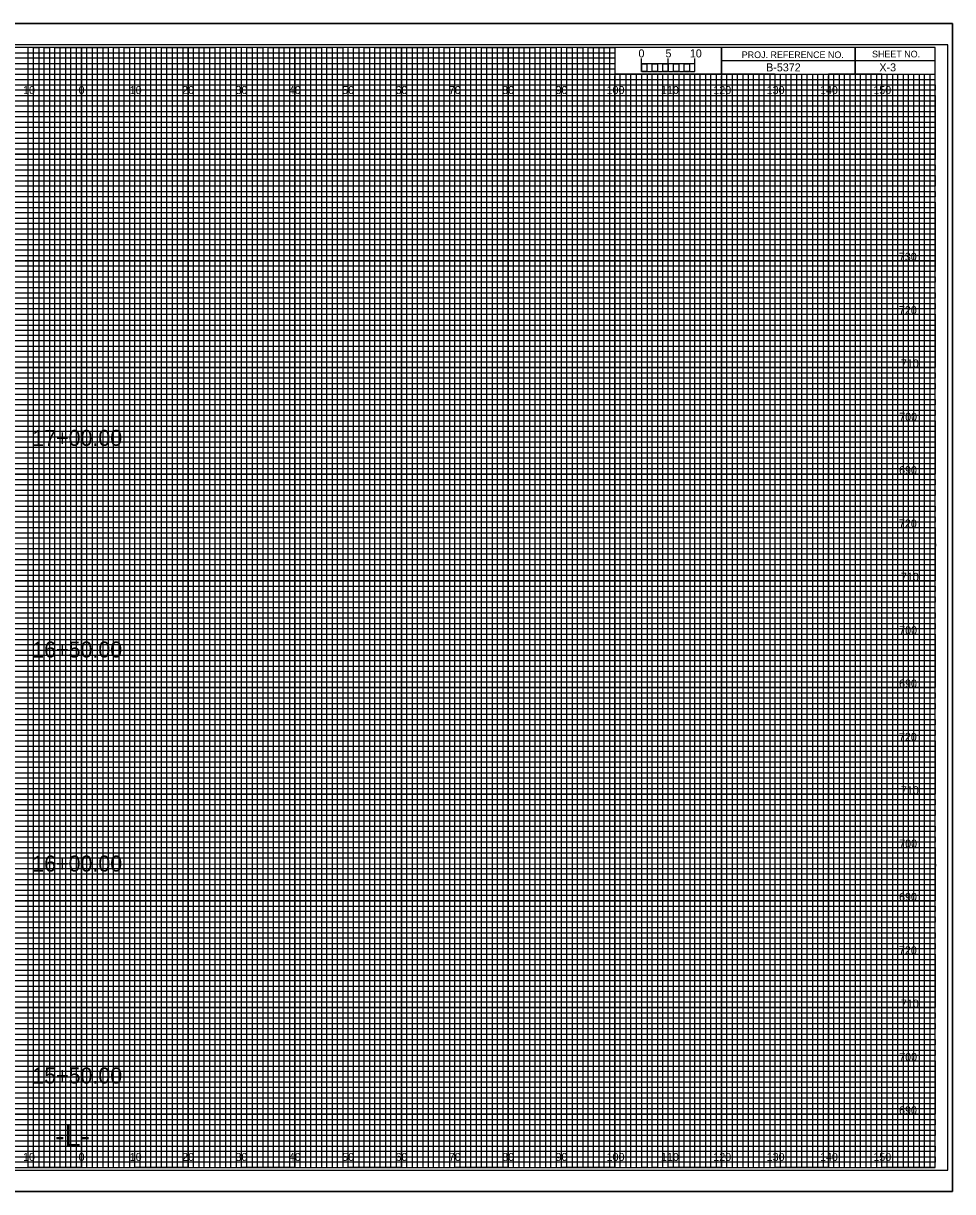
# Model space of a CAD drawing. Extents: x -98 to 717, y -10 to 1974.
# Drawn here: x 149.1 to 323.3, y 435.5 to 654.5 of the extents above; entities that cross this region are included whole.
import ezdxf

# ---------------------------------------------------------------- set-up
doc = ezdxf.new("R2010")
doc.units = 0
for name, color, linetype in [('Default', 7, 'Continuous'), ('Exist XS Center Line Elevation Label', 7, 'Continuous'), ('Prop CMT Conc Surface', 7, 'Continuous'), ('Prop CMT Concrete Structures', 7, 'Continuous'), ('Prop CMT Pvmt Course 1', 7, 'Continuous'), ('Prop CMT Pvmt Course 1 CG', 7, 'Continuous'), ('Prop CMT Pvmt Course 2', 7, 'Continuous'), ('Prop CMT Pvmt Course 3', 7, 'Continuous'), ('Prop CMT Pvmt Surface', 7, 'Continuous'), ('Prop CMT Pvmt Surface Shoulder', 7, 'Continuous'), ('Prop CMT Shld Paved Course 1', 7, 'Continuous'), ('Prop CMT Shld Paved Course 2', 7, 'Continuous'), ('Prop CMT Shld Paved Course 3', 7, 'Continuous'), ('Prop CMT Slope Grass', 7, 'Continuous'), ('Prop CMT Subgrade Earthwork', 7, 'Continuous'), ('Prop XS Earthwork Shape', 7, 'Continuous'), ('Prop XS Elevation Labels', 7, 'Continuous'), ('Typical Curb CELL', 7, 'Continuous')]:
    doc.layers.add(name, color=color, linetype=linetype)

msp = doc.modelspace()

# ---------------------------------------------------------------- linework, layer by layer
at = {"layer": 'Default'}
msp.add_lwpolyline([(323.3, 435.5), (-13.4, 435.5), (-13.4, 654.5), (323.3, 654.5)], close=True, dxfattribs=at)
at = {"layer": 'Exist XS Center Line Elevation Label'}
for p, q in [((0, 649), (260, 649)), ((260, 649), (260, 647.98)), ((260, 647.98), (0, 647.98)), ((0, 647), (260, 647)), ((260, 647), (260, 645.89)), ((260, 645.89), (0, 645.89)), ((0, 644), (320, 644))]:
    msp.add_line(p, q, dxfattribs=at)
for points in [[(0, 643), (270, 643), (320, 643), (320, 642), (0, 642)], [(0, 641), (320, 641), (320, 639), (0, 639)], [(0, 638), (320, 638), (320, 637), (0, 636.98)], [(0, 636), (320, 636), (320, 634), (0, 634)], [(0, 633), (320, 633), (320, 632), (0, 632)], [(0, 631), (320, 631), (320, 629), (0, 629)], [(0, 628), (320, 628), (320, 627), (0, 627)], [(0, 626), (320, 626), (320, 624), (0, 624)], [(0, 623), (320, 623), (320, 622), (0, 622)], [(0, 621), (320, 621), (320, 619), (0, 619)], [(0, 618), (320, 618), (320, 617), (0, 617)], [(0, 616), (320, 616), (320, 613.95), (320, 613), (320, 612), (0, 612)], [(0, 614), (320, 614), (320, 613), (0, 613)], [(0, 611), (320, 611), (320, 609), (0, 609.03)], [(0, 609.03), (320, 609), (320, 608), (0, 608)], [(0, 607), (320, 607), (320, 606), (0, 606)], [(0, 604), (320, 604), (320, 603), (0, 603)], [(0, 602), (320, 602), (320, 601), (0, 601)], [(-0.07, 598.89), (320, 598.89), (320, 597.88), (-0.07, 597.88)], [(0, 597), (320, 597), (320, 596), (0, 596)], [(0, 594), (320, 594), (320, 593), (0, 593)], [(0, 592), (320, 592), (320, 591), (0, 591)], [(0, 589), (320, 589), (320, 588), (0, 588)], [(0, 587), (320, 587), (320, 586), (0, 586)], [(0, 584), (320, 584), (320, 583), (0, 583)], [(0, 582), (320, 582), (320, 581), (0, 581)], [(0, 579), (320, 579), (319.99, 577.98), (0, 578)], [(0, 577), (320, 577), (320, 576), (0, 576)], [(0, 574), (320, 574), (320, 573), (0, 573)], [(0, 572), (320, 572), (320, 571), (0, 571)], [(0, 569), (320, 569), (320, 568), (0, 568)], [(0, 567), (320, 567), (320, 566), (0, 566)], [(0, 564), (320, 564), (320, 563), (0, 563)], [(0, 562), (320, 562), (320, 561), (0, 561)], [(0, 559), (320, 559), (320, 558), (0, 558)], [(0, 556.99), (320.07, 556.91), (320, 556), (0, 556)], [(0, 554), (320, 554), (320, 553), (0, 553)], [(0, 552), (320, 552), (320, 551), (0, 551)], [(0, 549), (320, 549), (320, 548), (0, 548)], [(0, 547), (320, 547), (320, 546), (0, 546)], [(0, 544), (320, 544), (320, 543), (0, 543)], [(0, 542), (320, 542), (320, 541), (0, 541)], [(0, 539), (320, 539), (320, 538), (0, 538)], [(0, 537), (320, 537), (320, 536), (0, 536)], [(0, 534), (320, 534), (320, 533), (0, 533)], [(0, 532), (320, 532), (320, 531), (0, 531)], [(0, 529), (320, 529), (320, 528), (0, 528)], [(0, 527), (320, 527), (320, 526), (0, 526)], [(0, 524), (320, 524), (320, 523), (0, 523)], [(0, 522), (320, 522), (320, 521), (0, 521)], [(0, 519), (320, 519), (319.99, 517.98), (0, 518)], [(0, 517), (320, 517), (320, 516), (0, 516)], [(0, 514), (320, 514), (320, 513), (0, 513)], [(0, 512), (320, 512), (320, 511), (0, 511)], [(0, 509), (320, 509), (320, 508), (0, 508)], [(0, 507), (320, 507), (320, 506), (0, 506)], [(0, 504), (320, 504), (320, 503), (0, 503)], [(0, 502), (320, 502), (320, 501), (0, 501)], [(0, 499), (320, 499), (320, 498), (0, 498)], [(0, 496.99), (320.07, 496.91), (320, 496), (0, 496)], [(0, 494), (320, 494), (320, 493), (0, 493)], [(0, 492), (320, 492), (320, 491), (0, 491)], [(0, 489), (320, 489), (320, 488), (0, 488)], [(0, 487), (320, 487), (320, 486), (0, 486)], [(0, 484), (320, 484), (320, 483), (0, 483)], [(0, 482), (320, 482), (320, 481), (0, 481)], [(0, 479), (320, 479), (320, 478), (0, 478)], [(0, 477), (320, 477), (320, 476), (0, 476)], [(0, 474), (320, 474), (320, 473), (0, 473)], [(0, 472), (320, 472), (320, 471), (0, 471)], [(0, 469), (320, 469), (320, 468), (0, 468)], [(0, 467), (320, 467), (320, 466), (0, 466)], [(0, 464), (320, 464), (320, 463), (0, 463)], [(0, 462), (320, 462), (320, 461), (0, 461)], [(0, 459), (320, 459), (320, 458), (0, 458)], [(0, 457), (320, 457), (320, 456), (0, 456)], [(0, 454), (320, 454), (320, 453), (0, 453)], [(0, 452), (320, 452), (320, 451), (0, 451)], [(0, 449), (320, 449), (320, 448), (0, 448)], [(0, 447), (320, 447), (320, 446), (0, 446)], [(0, 444), (320, 444), (320, 443), (0, 443)], [(0, 442), (320, 442), (320, 441), (0, 441)]]:
    msp.add_lwpolyline(points, dxfattribs=at)
at = {"layer": 'Prop CMT Conc Surface'}
for p, q in [((305, 650), (305, 645)), ((305, 645), (305, 650)), ((280, 647.5), (280, 645)), ((320, 647.49), (280, 647.49)), ((280, 645), (320, 645))]:
    msp.add_line(p, q, dxfattribs=at)
for points in [[(320, 650), (0, 650), (0, 440), (320, 440)], [(280, 650), (260, 650), (260, 645.03), (280, 645.03)], [(320, 650), (280, 650), (280, 645), (320, 645)]]:
    msp.add_lwpolyline(points, close=True, dxfattribs=at)
at = {"layer": 'Prop CMT Concrete Structures'}
for p, q in [((150, 440), (150, 650)), ((160, 440), (160, 650)), ((170, 440), (170, 650)), ((180, 440), (180, 650)), ((190, 440), (190, 650)), ((200, 440), (200, 650)), ((210, 440), (210, 650)), ((220, 440), (220, 650)), ((230, 440), (230, 650)), ((240, 440), (240, 650)), ((250, 440), (250, 650)), ((260, 440), (260, 644.69)), ((270, 440), (270, 644.69)), ((280, 440), (280, 644.69)), ((290, 440), (290, 644.69)), ((300, 440), (300, 644.69)), ((310, 440), (310, 644.69)), ((0, 640), (320, 640)), ((0, 630), (320, 630)), ((0, 620), (320, 620)), ((0, 610), (320, 610)), ((0, 600), (320, 600)), ((0, 590), (320, 590)), ((0, 580), (320, 580)), ((0, 570), (320, 570)), ((0, 560), (320, 560)), ((0, 550), (320, 550)), ((0, 540), (320, 540)), ((0, 530), (320, 530)), ((0, 520), (320, 520)), ((0, 510), (320, 510)), ((0, 500), (320, 500)), ((0, 490), (320, 490)), ((0, 480), (320, 480)), ((0, 470), (320, 470)), ((0, 460), (320, 460)), ((0, 450), (320, 450))]:
    msp.add_line(p, q, dxfattribs=at)
at = {"layer": 'Prop CMT Pvmt Course 2'}
msp.add_lwpolyline([(-13.4, 435.5), (323.3, 435.5), (323.3, 654.5), (-13.4, 654.5)], close=True, dxfattribs=at)
at = {"layer": 'Prop CMT Pvmt Course 3'}
msp.add_lwpolyline([(-10.8, 439.5), (322.4, 439.5), (322.4, 650.5), (-10.8, 650.5)], close=True, dxfattribs=at)
at = {"layer": 'Prop CMT Pvmt Surface'}
for p, q in [((323.3, 654.5), (-13.4, 654.5)), ((-13.4, 435.5), (323.3, 435.5))]:
    msp.add_line(p, q, dxfattribs=at)
at = {"layer": 'Prop CMT Slope Grass'}
for p, q in [((265, 645.49), (265, 647.9)), ((265, 646.9), (265, 647.9)), ((270, 645.49), (270, 647.9)), ((275, 645.49), (275, 647.9)), ((275, 646.9), (275, 647.9))]:
    msp.add_line(p, q, dxfattribs=at)
for points in [[(275, 646.9), (265, 646.9), (265, 645.49), (275, 645.49)], [(265, 646.9), (266, 646.9), (266, 645.49), (265, 645.49)], [(267, 646.9), (268, 646.9), (268, 645.49), (267, 645.49)], [(269, 646.9), (270, 646.9), (270, 645.49), (269, 645.49)], [(271, 646.9), (272, 646.9), (272, 645.49), (271, 645.49)], [(273, 646.9), (274, 646.9), (274, 645.49), (273, 645.49)]]:
    msp.add_lwpolyline(points, close=True, dxfattribs=at)
at = {"layer": 'Prop CMT Subgrade Earthwork'}
for p, q in [((267, 645), (266.01, 645)), ((266.01, 645), (266.01, 440)), ((267, 440), (267, 645)), ((269, 645), (268, 645)), ((268, 645), (268, 440)), ((269, 440), (269, 645)), ((266.01, 440), (265, 440)), ((268, 440), (267, 440))]:
    msp.add_line(p, q, dxfattribs=at)
for points in [[(150, 440), (151, 440), (151, 650), (152, 650), (152, 440)], [(152, 440), (153, 440), (153, 650), (154, 650), (154, 440)], [(155, 440), (156, 440), (156, 650), (157, 650), (157, 440)], [(157, 440), (158, 440), (158, 650), (159, 650), (159, 440)], [(160, 440), (161, 440), (161, 650), (162, 650), (162, 440)], [(162, 440), (163, 440), (163, 650), (164, 650), (164, 440)], [(165, 440), (166, 440), (166, 650), (167, 650), (167, 440)], [(167, 440), (168, 440), (168, 650), (169, 650), (169, 440)], [(170, 440), (171, 440), (171, 650), (172, 650), (172, 440)], [(172, 440), (173, 440), (173, 650), (174, 650), (174, 440)], [(175, 440), (176, 440), (176, 650), (177, 650), (177, 440)], [(177, 440), (178, 440), (178, 650), (179, 650), (179, 440)], [(180, 440), (181, 440), (181, 650), (182, 650), (182, 440)], [(182, 440), (183, 440), (183, 650), (184, 650), (184, 440)], [(185, 440), (186, 440), (186, 650), (187, 650), (187, 440)], [(187, 440), (188, 440), (188, 650), (189, 650), (189, 440)], [(190, 440), (191, 440), (191, 650), (192, 650), (192, 440)], [(192, 440), (193, 440), (193, 650), (194, 650), (194, 440)], [(195, 440), (196, 440), (196, 650), (197, 650), (197, 440)], [(197, 440), (198, 440), (198, 650), (199, 650), (199, 440)], [(200, 440), (201, 440), (201, 650), (202, 650), (202, 440)], [(202, 440), (203, 440), (203, 650), (204, 650), (204, 440)], [(205, 440), (206, 440), (206, 650), (207, 650), (207, 440)], [(207, 440), (208, 440), (208, 650), (209, 650), (209, 440)], [(210, 440), (211, 440), (211, 650), (212, 650), (212, 440)], [(212, 440), (213, 440), (213, 650), (214, 650), (214, 440)], [(215, 440), (216, 440), (216, 650), (217, 650), (217, 440)], [(217, 440), (218, 440), (218, 650), (219, 650), (219, 440)], [(220, 440), (221, 440), (221, 650), (222, 650), (222, 440)], [(222, 440), (223, 440), (223, 650), (224, 650), (224, 440)], [(225, 440), (226, 440), (226, 650), (227, 650), (227, 440)], [(227, 440), (228, 440), (228, 650), (229, 650), (229, 440)], [(230, 440), (231, 440), (231, 650), (232, 650), (232, 440)], [(232, 440), (233, 440), (233, 650), (234, 650), (234, 440)], [(235, 440), (236, 440), (236, 650), (237, 650), (237, 440)], [(237, 440), (238, 440), (238, 650), (239, 650), (239, 440)], [(240, 440), (241, 440), (241, 650), (242, 650), (242, 440)], [(242, 440), (243, 440), (243, 650), (244, 650), (244, 440)], [(245, 440), (246, 440), (246, 650), (247, 650), (247, 440)], [(247, 440), (248, 440), (248, 650), (249, 650), (249, 440)], [(250, 440), (251, 440), (251, 650), (252, 650), (252, 440)], [(252, 440), (253, 440), (253, 650), (254, 650), (254, 440)], [(255, 440), (256, 440), (256, 650), (257, 650), (257, 440)], [(257, 440), (258, 440), (258, 650), (259, 650), (259, 440)], [(260, 440), (261, 440), (261, 645), (262.02, 645), (262.02, 440)], [(262, 440), (263, 440), (263, 645), (263.99, 645), (263.99, 440)], [(270, 440), (270.98, 440), (270.98, 645), (272, 645), (272, 440)], [(272, 440), (273, 440), (273, 645), (274.05, 645), (274.05, 440)], [(275, 440), (276, 440), (276, 645), (277, 645), (277, 440)], [(277, 440), (278, 440), (278, 645), (279, 645), (279, 440)], [(280, 440), (281, 440), (281, 645), (282, 645), (282, 440)], [(282, 440), (283, 440), (283, 645), (284, 645), (284, 440)], [(285, 440), (286, 440), (286, 645), (287, 645), (287, 440)], [(287, 440), (288, 440), (288, 645), (289, 645), (289, 440)], [(290, 440), (291, 440), (291, 645), (292, 645), (292, 440)], [(292, 440), (293, 440), (293, 645), (294, 645), (294, 440)], [(295, 440), (296, 440), (296, 645), (297, 645), (297, 440)], [(297, 440), (298, 440), (298, 645), (299, 645), (299, 440)], [(300, 440), (301, 440), (301, 645), (302, 645), (302, 440)], [(302, 440), (303, 440), (303, 645), (304, 645), (304, 440)], [(305, 440), (306, 440), (306, 645), (307, 645), (307, 440)], [(307, 440), (308, 440), (308, 645), (309, 645), (309, 440)], [(310, 440), (311, 440), (311, 645), (312, 645), (312, 440)], [(312, 440), (313, 440), (313, 645), (314, 645), (314, 440)], [(315, 440), (316, 440), (316, 645), (317, 645), (317, 440)], [(317, 440), (318, 440), (318, 645), (319, 645), (319, 440)]]:
    msp.add_lwpolyline(points, dxfattribs=at)
at = {"layer": 'Prop XS Elevation Labels'}
for p, q in [((150, 650), (140, 650)), ((150, 440), (150, 650)), ((170, 650), (160, 650)), ((160, 650), (160, 440)), ((170, 440), (170, 650)), ((190, 650), (180, 650)), ((180, 650), (180, 440)), ((190, 440), (190, 650)), ((210, 650), (200, 650)), ((200, 650), (200, 440)), ((210, 440), (210, 650)), ((230, 650), (220, 650)), ((220, 650), (220, 440)), ((230, 440), (230, 650)), ((250, 650), (240, 650)), ((240, 650), (240, 440)), ((250, 440), (250, 650)), ((260, 650), (260, 440)), ((270, 440), (270, 645)), ((290, 645), (280, 645)), ((280, 645), (280, 440)), ((290, 440), (290, 645)), ((310, 645), (300, 645)), ((300, 645), (300, 440)), ((310, 440), (310, 645)), ((160, 440), (150, 440)), ((180, 440), (170, 440)), ((200, 440), (190, 440)), ((220, 440), (210, 440)), ((240, 440), (230, 440)), ((260, 440), (250, 440)), ((280, 440), (270, 440)), ((300, 440), (290, 440)), ((320, 440), (310, 440)), ((320, 440), (320, 440))]:
    msp.add_line(p, q, dxfattribs=at)
for points in [[(0, 640), (320, 640), (320, 630), (0, 630)], [(0, 620), (320, 620), (320, 610), (0, 610)], [(0, 600), (320, 600), (320, 590), (0, 590)], [(0, 580), (320, 580), (320, 570), (0, 570)], [(0, 560), (320, 560), (320, 550), (0, 550)], [(0, 540), (320, 540), (320, 530), (0, 530)], [(0, 520), (320, 520), (320, 510), (0, 510)], [(0, 500), (320, 500), (320, 490), (0, 490)], [(0, 480), (320, 480), (320, 470), (0, 470)], [(0, 460), (320, 460), (320, 450), (0, 450)]]:
    msp.add_lwpolyline(points, dxfattribs=at)
at = {"layer": 'Typical Curb CELL'}
for points in [[(145, 440), (155, 440), (155, 650), (165, 650), (165, 440), (175, 440), (175, 650), (185, 650), (185, 440), (195, 440), (195, 650), (205, 650), (205, 440), (215, 440), (215, 650), (225, 650), (225, 440), (235, 440), (235, 650), (245, 650), (245, 440), (255, 440), (255, 650), (259.93, 650), (260, 650), (260, 645), (264.99, 645), (264.99, 440), (275, 440), (275, 645), (285, 645), (285, 440), (295, 440), (295, 645), (305, 645), (305, 440), (315, 440), (315, 645)], [(0, 645), (275, 645)], [(0, 625), (320, 625), (320, 635), (0, 635)], [(0, 605), (320, 605), (320, 615), (0, 615)], [(0, 585), (320, 585), (320, 595), (0, 595)], [(0, 565), (320, 565), (320, 575), (0, 575)], [(0, 545), (320, 545), (320, 555), (0, 555)], [(0, 525), (320, 525), (320, 535), (0, 535)], [(0, 505), (320, 505), (320, 515), (0, 515)], [(0, 485), (320, 485), (320, 495), (0, 495)], [(0, 465), (320, 465), (320, 475), (0, 475)], [(0, 445), (320, 445), (320, 455), (0, 455)]]:
    msp.add_lwpolyline(points, dxfattribs=at)

# ---------------------------------------------------------------- texts
at = {"layer": 'Prop CMT Conc Surface'}
for s, p in [('PROJ. REFERENCE NO.', (283.77, 647.99)), ('SHEET NO.', (308.19, 648.12))]:
    msp.add_text(s, height=1.25, dxfattribs=at).set_placement(p)
at = {"layer": 'Prop CMT Pvmt Course 1'}
for s, p in [('17+00.00', (150.77, 575.29)), ('16+50.00', (150.77, 535.62)), ('16+00.00', (150.77, 495.5)), ('15+50.00', (150.77, 455.77))]:
    msp.add_text(s, height=3, dxfattribs=at).set_placement(p)
at = {"layer": 'Prop CMT Pvmt Course 1 CG'}
for s, p in [('730', (313.22, 610)), ('720', (313.23, 600)), ('710', (313.61, 590)), ('700', (313.28, 580)), ('690', (313.26, 570)), ('720', (313.23, 560)), ('710', (313.61, 550)), ('700', (313.28, 540)), ('690', (313.26, 530)), ('720', (313.23, 520)), ('710', (313.61, 510)), ('700', (313.28, 500)), ('690', (313.26, 490)), ('720', (313.23, 480)), ('710', (313.61, 470)), ('700', (313.28, 460)), ('690', (313.26, 450))]:
    msp.add_text(s, height=1.5, dxfattribs=at).set_placement(p)
at = {"layer": 'Prop CMT Pvmt Surface Shoulder'}
for s, p in [('5', (269.47, 648.12)), ('10', (274.04, 648.12))]:
    msp.add_text(s, height=1.5, dxfattribs=at).set_placement(p)
at = {"layer": 'Prop CMT Shld Paved Course 1'}
msp.add_text('X-3', height=1.5, dxfattribs=at).set_placement((309.57, 645.5))
at = {"layer": 'Prop CMT Shld Paved Course 2'}
msp.add_text('B-5372', height=1.5, dxfattribs=at).set_placement((288.34, 645.5))
at = {"layer": 'Prop CMT Shld Paved Course 3'}
msp.add_text('-L-', height=4, dxfattribs=at).set_placement((155.06, 444))
at = {"layer": 'Prop CMT Slope Grass'}
msp.add_text('0', height=1.5, dxfattribs=at).set_placement((264.41, 648.12))
at = {"layer": 'Prop XS Earthwork Shape'}
for s, p in [('10', (149.04, 641.25)), ('0', (159.45, 641.25)), ('0', (159.45, 641.25)), ('10', (169.04, 641.25)), ('20', (178.86, 641.25)), ('30', (188.86, 641.25)), ('40', (198.86, 641.25)), ('50', (208.86, 641.25)), ('60', (218.86, 641.25)), ('70', (228.86, 641.25)), ('80', (238.86, 641.25)), ('90', (248.86, 641.25)), ('100', (258.44, 641.25)), ('110', (268.62, 641.25)), ('120', (278.44, 641.25)), ('130', (288.44, 641.25)), ('140', (298.44, 641.25)), ('150', (308.44, 641.25)), ('10', (149.04, 441.25)), ('0', (159.45, 441.25)), ('0', (159.45, 441.25)), ('10', (169.04, 441.25)), ('20', (178.86, 441.25)), ('30', (188.86, 441.25)), ('40', (198.86, 441.25)), ('50', (208.86, 441.25)), ('60', (218.86, 441.25)), ('70', (228.86, 441.25)), ('80', (238.86, 441.25)), ('90', (248.86, 441.25)), ('100', (258.44, 441.25)), ('110', (268.62, 441.25)), ('120', (278.44, 441.25)), ('130', (288.44, 441.25)), ('140', (298.44, 441.25)), ('150', (308.44, 441.25))]:
    msp.add_text(s, height=1.5, dxfattribs=at).set_placement(p)

doc.saveas('drawing.dxf')
